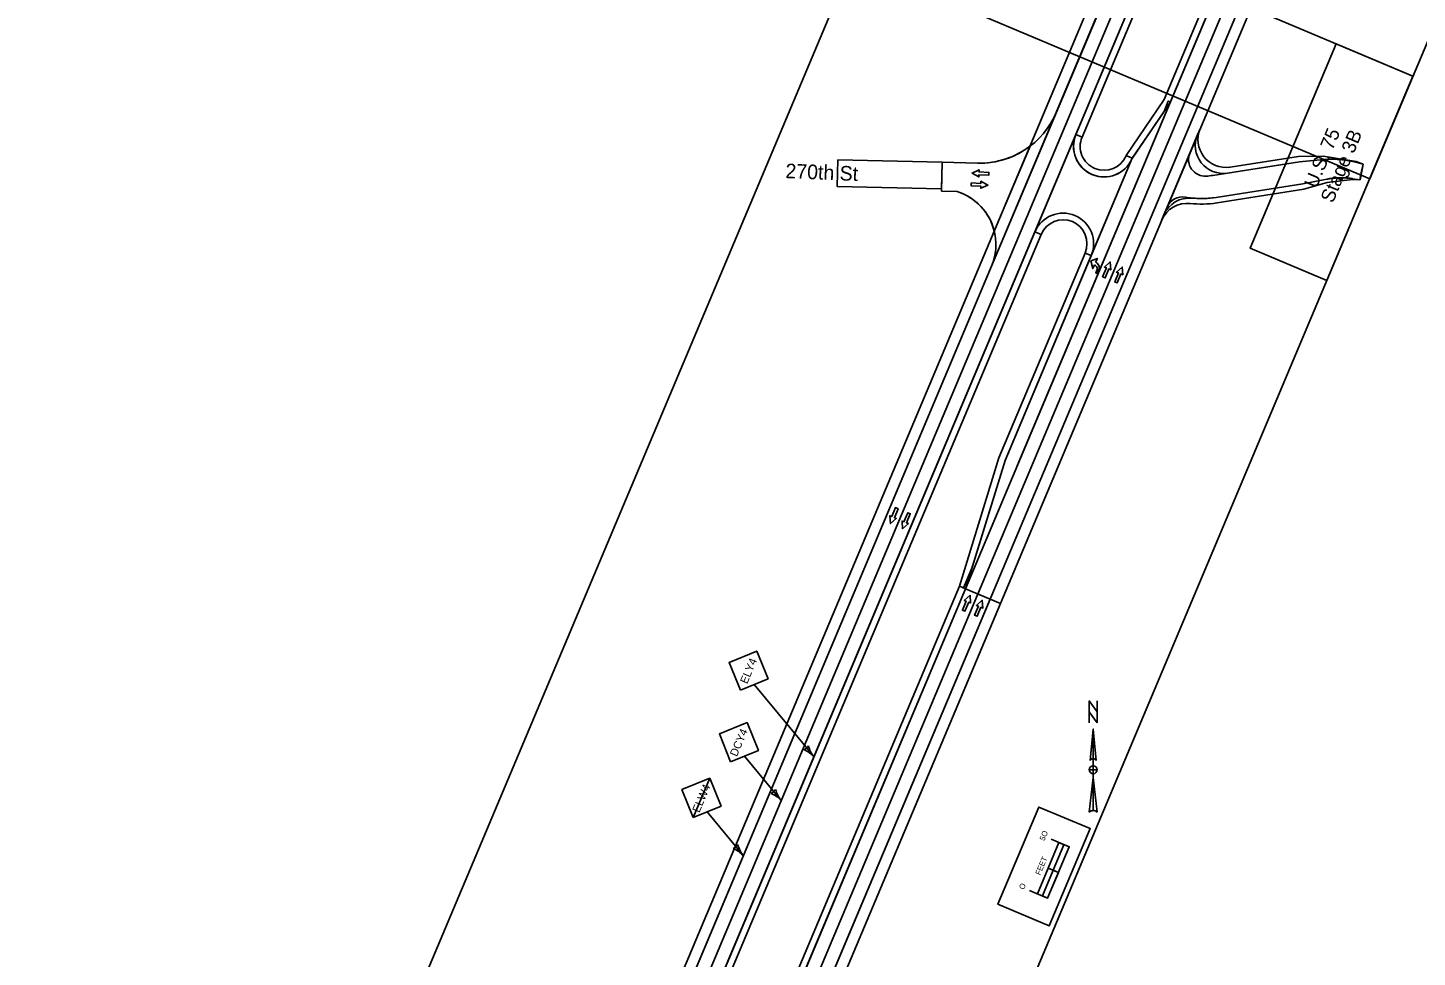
# Model space of a CAD drawing. Extents: x 14104283 to 14120882, y 8635219 to 8671666.
# Drawn here: x 14110477 to 14111728, y 8650037 to 8650873 of the extents above; entities that cross this region are included whole.
import ezdxf

# ---------------------------------------------------------------- set-up
doc = ezdxf.new("R2010")
doc.units = 0
for name, color, linetype in [('Cell', 7, 'Continuous'), ('dsnCellsNorthArrow', 7, 'Continuous'), ('dsnCellsScaleBlock', 7, 'Continuous'), ('dsnNonPlotable', 7, 'Continuous'), ('dsnPaintExistingBrokenLaneLineWhite', 7, 'Continuous'), ('dsnPaintExistingEdgeLineLeftYellow', 7, 'Continuous'), ('dsnPaintExistingEdgeLineRightWhite', 7, 'Continuous'), ('dsnPaintExistingLaneLineWhite', 7, 'Continuous'), ('dsnShadingGranular', 7, 'Continuous'), ('dsnShadingPaved', 7, 'Continuous'), ('dsnStdLabel', 7, 'Continuous'), ('dsnStgShadingPrevPav', 7, 'Continuous'), ('dsnTextFinalPlan', 7, 'Continuous'), ('dsnTextOverlapEven', 7, 'Continuous')]:
    doc.layers.add(name, color=color, linetype=linetype)

msp = doc.modelspace()

# ---------------------------------------------------------------- linework, layer by layer
at = {"layer": 'Cell'}
for p, q in [((14111438.2, 8650662.2), (14111438.4, 8650662.1)), ((14111437.4, 8650659.6), (14111437.1, 8650659.8))]:
    msp.add_line(p, q, dxfattribs=at)
for points in [[(14111342.1, 8650742.9), (14111342, 8650740.4), (14111333.2, 8650740.8), (14111333.1, 8650738.9), (14111327, 8650742.3), (14111333.4, 8650745.1), (14111333.3, 8650743.3)], [(14111326.1, 8650730.9), (14111326.2, 8650733.4), (14111335, 8650733), (14111335, 8650734.9), (14111341.2, 8650731.5), (14111334.8, 8650728.6), (14111334.9, 8650730.5)], [(14111446.9, 8650648), (14111444.5, 8650649), (14111447.9, 8650657.1), (14111446.1, 8650657.8), (14111451.4, 8650662.4), (14111451.9, 8650655.4), (14111450.2, 8650656.1)], [(14111457.7, 8650643.5), (14111455.4, 8650644.4), (14111458.7, 8650652.5), (14111456.9, 8650653.2), (14111462.2, 8650657.8), (14111462.7, 8650650.9), (14111461, 8650651.6)], [(14111258.1, 8650441.5), (14111260.4, 8650440.5), (14111257.1, 8650432.4), (14111258.8, 8650431.7), (14111253.5, 8650427.1), (14111253, 8650434.1), (14111254.7, 8650433.4)], [(14111269.1, 8650436.8), (14111271.4, 8650435.9), (14111268, 8650427.8), (14111269.8, 8650427.1), (14111264.5, 8650422.5), (14111264, 8650429.4), (14111265.7, 8650428.7)], [(14111320.6, 8650348.3), (14111318.3, 8650349.2), (14111321.6, 8650357.3), (14111319.9, 8650358), (14111325.2, 8650362.6), (14111325.7, 8650355.7), (14111324, 8650356.4)], [(14111331.6, 8650343.7), (14111329.3, 8650344.7), (14111332.7, 8650352.8), (14111330.9, 8650353.5), (14111336.2, 8650358.1), (14111336.7, 8650351.1), (14111335, 8650351.8)]]:
    msp.add_lwpolyline(points, close=True, dxfattribs=at)
for points in [[(14111333.3, 8650743.3), (14111333.4, 8650745.1), (14111327, 8650742.3), (14111333.1, 8650738.9), (14111333.2, 8650740.8), (14111342, 8650740.4), (14111342.1, 8650742.9), (14111333.3, 8650743.3)], [(14111334.9, 8650730.5), (14111334.8, 8650728.6), (14111341.2, 8650731.5), (14111335, 8650734.9), (14111335, 8650733), (14111326.2, 8650733.4), (14111326.1, 8650730.9), (14111334.9, 8650730.5)], [(14111434, 8650663.3), (14111439.8, 8650665.5), (14111438.2, 8650662.2)], [(14111434, 8650663.3), (14111439.8, 8650665.5), (14111438.2, 8650662.2)], [(14111437.1, 8650659.8), (14111435.6, 8650656.4), (14111434, 8650663.3)], [(14111437.1, 8650659.8), (14111435.6, 8650656.4), (14111434, 8650663.3)], [(14111438.2, 8650662.2), (14111438.4, 8650662.1)], [(14111450.2, 8650656.1), (14111451.9, 8650655.4), (14111451.4, 8650662.4), (14111446.1, 8650657.8), (14111447.9, 8650657.1), (14111444.5, 8650649), (14111446.9, 8650648), (14111450.2, 8650656.1)], [(14111437.4, 8650659.6), (14111437.1, 8650659.8)], [(14111441, 8650655.3), (14111439.7, 8650651.9), (14111438.3, 8650652.5), (14111439.3, 8650654.9)], [(14111441, 8650655.3), (14111439.7, 8650651.9), (14111438.3, 8650652.5), (14111439.3, 8650654.9)], [(14111461, 8650651.6), (14111462.7, 8650650.9), (14111462.2, 8650657.8), (14111456.9, 8650653.2), (14111458.7, 8650652.5), (14111455.4, 8650644.4), (14111457.7, 8650643.5), (14111461, 8650651.6)], [(14111254.7, 8650433.4), (14111253, 8650434.1), (14111253.5, 8650427.1), (14111258.8, 8650431.7), (14111257.1, 8650432.4), (14111260.4, 8650440.5), (14111258.1, 8650441.5), (14111254.7, 8650433.4)], [(14111265.7, 8650428.7), (14111264, 8650429.4), (14111264.5, 8650422.5), (14111269.8, 8650427.1), (14111268, 8650427.8), (14111271.4, 8650435.9), (14111269.1, 8650436.8), (14111265.7, 8650428.7)], [(14111324, 8650356.4), (14111325.7, 8650355.7), (14111325.2, 8650362.6), (14111319.9, 8650358), (14111321.6, 8650357.3), (14111318.3, 8650349.2), (14111320.6, 8650348.3), (14111324, 8650356.4)], [(14111335, 8650351.8), (14111336.7, 8650351.1), (14111336.2, 8650358.1), (14111330.9, 8650353.5), (14111332.7, 8650352.8), (14111329.3, 8650344.7), (14111331.6, 8650343.7), (14111335, 8650351.8)]]:
    msp.add_lwpolyline(points, dxfattribs=at)
for centre, major_axis in [((14111436, 8650656.2), (-1.38, -3.41)), ((14111436, 8650656.2), (-1.38, -3.41)), ((14111436.4, 8650657.2), (-1.97, -4.87)), ((14111436.4, 8650657.2), (-1.97, -4.87))]:
    msp.add_ellipse(centre, major_axis=major_axis, ratio=0.9474, start_param=1.570796, end_param=3.141593, dxfattribs=at)
at = {"layer": 'dsnCellsNorthArrow'}
for p, q in [((14111436, 8650242.3), (14111438.8, 8650214.1)), ((14111436, 8650242.3), (14111436, 8650169)), ((14111433.2, 8650214.1), (14111433.2, 8650214.1)), ((14111433.3, 8650214.4), (14111433.8, 8650215)), ((14111436, 8650202.1), (14111436, 8650202.1)), ((14111432.4, 8650167.6), (14111436, 8650198.6))]:
    msp.add_line(p, q, dxfattribs=at)
msp.add_lwpolyline([(14111439.5, 8650247.9), (14111432.4, 8650257.8), (14111432.4, 8650267.6), (14111439.5, 8650257.8)], close=True, dxfattribs=at)
for points in [[(14111432.4, 8650247.9), (14111432.4, 8650267.6), (14111439.5, 8650257.8), (14111439.5, 8650267.6)], [(14111433.2, 8650214.1), (14111436, 8650242.3), (14111436, 8650215.5)], [(14111436, 8650202.1), (14111436, 8650205.7), (14111432.4, 8650205.7)], [(14111439.5, 8650205.7), (14111436, 8650205.7), (14111436, 8650209.2)], [(14111436, 8650169), (14111436, 8650198.6), (14111439.5, 8650167.6)]]:
    msp.add_lwpolyline(points, dxfattribs=at)
for centre, radius, start, end in [((14111436, 8650212), 3.52, 90.0204, 143.1257), ((14111436, 8650212), 3.52, 36.8481, 90.0218), ((14111436, 8650205.7), 3.52, 90, 180), ((14111436, 8650205.7), 3.52, 180, 270), ((14111436, 8650205.7), 3.52, 0, 90), ((14111436, 8650205.7), 3.52, 270, 360), ((14111436, 8650163.9), 5.1, 89.9894, 133.619), ((14111436, 8650163.9), 5.11, 46.4021, 90.0006)]:
    msp.add_arc(centre, radius, start, end, dxfattribs=at)
at = {"layer": 'dsnCellsScaleBlock'}
msp.add_line((14111404.7, 8650113.3), (14111395.5, 8650117.2), dxfattribs=at)
msp.add_line((14111404.7, 8650113.3), (14111395.5, 8650117.2), dxfattribs=at)
for points in [[(14111396.4, 8650065.3), (14111350.3, 8650084.7), (14111387.2, 8650172.2), (14111433.3, 8650152.8)], [(14111350.3, 8650084.7), (14111387.2, 8650172.2), (14111433.3, 8650152.8), (14111396.4, 8650065.3)], [(14111396.4, 8650065.3), (14111350.3, 8650084.7), (14111387.2, 8650172.2), (14111433.3, 8650152.8)], [(14111400, 8650115.3), (14111409.7, 8650138.3), (14111405.2, 8650140.3), (14111395.5, 8650117.2)], [(14111395, 8650090.3), (14111404.7, 8650113.3), (14111400, 8650115.3), (14111390.3, 8650092.2)]]:
    msp.add_lwpolyline(points, close=True, dxfattribs=at)
for points in [[(14111378.8, 8650097.1), (14111395, 8650090.3), (14111414.4, 8650136.4), (14111398.3, 8650143.2)], [(14111385.8, 8650094.2), (14111405.2, 8650140.3)]]:
    msp.add_lwpolyline(points, dxfattribs=at)
at = {"layer": 'dsnNonPlotable'}
for points in [[(14111219.5, 8650933.3), (14111828.1, 8652377.8), (14112293.5, 8652181.8), (14111684.9, 8650737.2)], [(14110649.8, 8649580.9), (14111258.3, 8651025.5), (14111723.7, 8650829.4), (14111115.1, 8649384.9)]]:
    msp.add_lwpolyline(points, close=True, dxfattribs=at)
at = {"layer": 'dsnPaintExistingBrokenLaneLineWhite'}
for p, q in [((14110829.5, 8649404.5), (14118424.3, 8667439.6)), ((14110913.3, 8649369.2), (14114932.5, 8658913.4))]:
    msp.add_line(p, q, dxfattribs=at)
at = {"layer": 'dsnPaintExistingEdgeLineLeftYellow'}
for p, q in [((14113594.8, 8655940.3), (14111420.5, 8650777)), ((14111505.3, 8650805.9), (14113533.3, 8655621.7)), ((14111470.9, 8650755.1), (14111505.3, 8650805.9)), ((14111356.7, 8650483.8), (14111434.3, 8650668.1)), ((14111321.1, 8650368.5), (14111356.7, 8650483.8)), ((14110902.3, 8649373.8), (14111321.1, 8650368.5))]:
    msp.add_line(p, q, dxfattribs=at)
msp.add_lwpolyline([(14111383.6, 8650689.4), (14110840.5, 8649399.8), (14109233.5, 8645585.3)], dxfattribs=at)
for centre, start, end in [((14111445.8, 8650766.3), 157.1633, 335.8501), ((14111408.9, 8650678.8), 67.1633, 156.8935), ((14111408.9, 8650678.8), 337.1465, 67.1633)]:
    msp.add_arc(centre, 27.5, start, end, dxfattribs=at)
at = {"layer": 'dsnPaintExistingEdgeLineRightWhite'}
for p, q in [((14110924.4, 8649364.5), (14118874.7, 8668243.7)), ((14113555.5, 8655908.7), (14111402.9, 8650797.1))]:
    msp.add_line(p, q, dxfattribs=at)
msp.add_lwpolyline([(14111344.6, 8650658.6), (14110818.4, 8649409.2), (14109217, 8645608.1)], dxfattribs=at)
at = {"layer": 'dsnPaintExistingLaneLineWhite'}
msp.add_line((14111367.7, 8650479.1), (14111445.3, 8650663.4), dxfattribs=at)
at = {"layer": 'dsnShadingGranular'}
msp.add_line((14111523, 8650760.3), (14111502.5, 8650711.7), dxfattribs=at)
at = {"layer": 'dsnShadingPaved'}
for p, q in [((14111505.5, 8650806.3), (14113533.3, 8655621.7)), ((14113555.5, 8655612.4), (14110924.4, 8649364.5)), ((14111321.1, 8650368.5), (14111505.5, 8650806.3)), ((14111505.3, 8650805.7), (14111321.1, 8650368.5)), ((14111470.6, 8650754.6), (14111505.3, 8650805.7)), ((14111402.9, 8650797.1), (14111344.6, 8650658.6)), ((14111383.6, 8650689.4), (14111420.5, 8650777)), ((14111299.6, 8650726), (14111300.2, 8650752)), ((14111300.2, 8650752), (14111332, 8650751.3)), ((14111313.6, 8650725.7), (14111299.6, 8650726)), ((14111356.7, 8650483.8), (14111434.3, 8650668.1)), ((14111321.1, 8650368.5), (14111356.7, 8650483.8)), ((14110902.3, 8649373.8), (14111321.1, 8650368.5))]:
    msp.add_line(p, q, dxfattribs=at)
for points in [[(14118413.2, 8667444.3), (14110818.4, 8649409.2), (14109142.6, 8645431.4)], [(14109164.7, 8645422.1), (14110840.5, 8649399.8), (14118435.4, 8667434.9)]]:
    msp.add_lwpolyline(points, dxfattribs=at)
for centre, radius, start, end in [((14111333.8, 8650826.2), 75, 268.6633, 337.1633), ((14111445.8, 8650766.3), 27.5, 157.1801, 247.1633), ((14111445.8, 8650766.3), 27.5, 247.1633, 335.8501), ((14111298.5, 8650678), 50, 337.1633, 72.4031), ((14111408.9, 8650678.8), 27.5, 67.1633, 156.8935), ((14111408.9, 8650678.8), 27.5, 337.1465, 67.1633)]:
    msp.add_arc(centre, radius, start, end, dxfattribs=at)
at = {"layer": 'dsnStdLabel'}
for p, q in [((14111131, 8650282.4), (14111184.8, 8650217.3)), ((14111122.2, 8650218), (14111155.2, 8650178.1)), ((14111076.1, 8650162.8), (14111090.9, 8650198)), ((14111088.6, 8650167.9), (14111121.2, 8650128.3))]:
    msp.add_line(p, q, dxfattribs=at)
for points in [[(14111118.5, 8650277.3), (14111143.5, 8650287.5), (14111133.3, 8650312.5), (14111108.3, 8650302.3)], [(14111109.7, 8650212.9), (14111134.7, 8650223.1), (14111124.6, 8650248.1), (14111099.6, 8650237.9)], [(14111076.1, 8650162.8), (14111101.1, 8650173), (14111090.9, 8650198), (14111065.9, 8650187.8)]]:
    msp.add_lwpolyline(points, close=True, dxfattribs=at)
for centre, radius, start, end in [((14111172.2, 8650231.9), 8.86, 292.8385, 328.307), ((14111202.2, 8650232.2), 22.9, 192.5015, 220.5728), ((14111167.3, 8650202.4), 22.9, 40.5727, 68.6439), ((14111142.7, 8650192.7), 8.86, 292.8385, 328.307), ((14111172.6, 8650193), 22.9, 192.5015, 220.5728), ((14111137.8, 8650163.1), 22.9, 40.5727, 68.6439), ((14111108.7, 8650143), 8.86, 292.8385, 328.307), ((14111138.7, 8650143.3), 22.9, 192.5015, 220.5728), ((14111103.8, 8650113.4), 22.9, 40.5727, 68.6439)]:
    msp.add_arc(centre, radius, start, end, dxfattribs=at)
at = {"layer": 'dsnStgShadingPrevPav'}
for p, q in [((14110809.2, 8649413), (14118404, 8667448.1)), ((14118413.2, 8667444.3), (14110818.4, 8649409.2)), ((14113594.8, 8655940.3), (14111420.5, 8650777)), ((14111402.9, 8650797.1), (14113555.5, 8655908.7)), ((14113533.3, 8655621.7), (14111505.5, 8650806.3)), ((14111352.5, 8650355.3), (14113564.7, 8655608.5)), ((14111505.5, 8650806.3), (14111321.1, 8650368.5)), ((14111344.6, 8650658.6), (14111402.9, 8650797.1)), ((14111383.6, 8650689.4), (14111420.5, 8650777)), ((14111420.5, 8650777), (14111383.6, 8650689.4)), ((14111420.5, 8650777), (14111426, 8650774.7)), ((14111529.9, 8650776.7), (14111523, 8650760.3)), ((14111532.2, 8650782.1), (14111529.9, 8650776.7)), ((14111379.2, 8650766.5), (14111347, 8650690.1)), ((14111299.6, 8650726), (14111300.2, 8650752)), ((14111300.2, 8650752), (14111332, 8650751.3)), ((14111471.1, 8650755.6), (14111434.3, 8650668.1)), ((14111465.6, 8650758), (14111471.1, 8650755.6)), ((14111523, 8650760.3), (14111502.5, 8650711.7)), ((14111621.5, 8650752.4), (14111543.5, 8650740.2)), ((14111556.8, 8650742.3), (14111621.5, 8650752.4)), ((14111620.7, 8650757.3), (14111559.1, 8650747.7)), ((14111642.9, 8650757.4), (14111620.7, 8650757.3)), ((14111643.4, 8650754.4), (14111621.5, 8650752.4)), ((14111621.5, 8650752.4), (14111643.4, 8650754.4)), ((14111678.8, 8650750.4), (14111672.4, 8650752.1)), ((14111672.4, 8650752.1), (14111678.8, 8650750.4)), ((14111675.9, 8650736.2), (14111678.8, 8650750.4)), ((14111678.8, 8650750.4), (14111677.5, 8650744)), ((14111677.8, 8650744), (14111679, 8650750.3)), ((14111543.5, 8650740.2), (14111556.8, 8650742.3)), ((14111669.4, 8650737.2), (14111675.9, 8650736.2)), ((14111675.9, 8650736.2), (14111669.4, 8650737.2)), ((14111677.5, 8650744), (14111675.9, 8650736.2)), ((14111676.2, 8650736.1), (14111677.8, 8650744)), ((14111677.8, 8650744), (14111677.5, 8650744)), ((14111677.5, 8650744), (14111677.8, 8650744)), ((14111313.6, 8650725.7), (14111299.6, 8650726)), ((14111546.6, 8650720.4), (14111624.6, 8650732.6)), ((14111624.6, 8650732.6), (14111546.6, 8650720.4)), ((14111547.4, 8650715.5), (14111625.4, 8650727.7)), ((14111624.6, 8650732.6), (14111646.1, 8650736.8)), ((14111646.1, 8650736.8), (14111624.6, 8650732.6)), ((14111625.4, 8650727.7), (14111646.6, 8650733.8)), ((14111499.6, 8650704.6), (14111497.5, 8650699.8)), ((14111502.5, 8650711.7), (14111499.6, 8650704.6)), ((14111389.1, 8650687.1), (14111383.6, 8650689.4)), ((14111434.3, 8650668.1), (14111428.7, 8650670.4)), ((14111321.1, 8650368.5), (14111352.5, 8650355.3))]:
    msp.add_line(p, q, dxfattribs=at)
for points in [[(14113600.3, 8655938), (14111426, 8650774.7), (14111420.5, 8650777), (14113594.8, 8655940.3)], [(14111465.6, 8650758), (14111500, 8650808.6), (14113527.8, 8655624.1), (14113533.3, 8655621.7), (14111505.5, 8650806.3), (14111503.6, 8650807.1), (14111499.8, 8650797.8), (14111471.1, 8650755.6)], [(14111321.1, 8650368.5), (14111319.3, 8650369.3), (14111327.1, 8650387.7), (14111356.7, 8650483.8), (14111471.1, 8650755.6), (14111499.8, 8650797.8), (14111503.6, 8650807.1), (14111505.5, 8650806.3)], [(14111299.6, 8650728), (14111205.7, 8650730.2), (14111206.3, 8650754.2), (14111300.2, 8650752)], [(14109239, 8645583), (14111389.1, 8650687.1), (14111383.6, 8650689.4), (14109233.5, 8645585.3)], [(14111315.6, 8650370.9), (14111351.1, 8650486.1), (14111428.7, 8650670.4), (14111434.3, 8650668.1), (14111356.7, 8650483.8), (14111327.1, 8650387.7), (14111319.3, 8650369.3)], [(14110622.7, 8648725.7), (14111315.6, 8650370.9), (14111321.1, 8650368.5), (14110628.3, 8648723.4)], [(14110902.3, 8649373.8), (14110924.4, 8649364.5), (14111343.3, 8650359.2), (14111321.1, 8650368.5)], [(14110933.6, 8649360.6), (14111352.5, 8650355.3), (14111343.3, 8650359.2), (14110924.4, 8649364.5)]]:
    msp.add_lwpolyline(points, close=True, dxfattribs=at)
for points in [[(14111679, 8650750.3), (14111672.5, 8650752.7), (14111642.9, 8650757.4)], [(14111646.6, 8650733.8), (14111669.3, 8650736.6), (14111676.2, 8650736.1)], [(14111383.6, 8650689.4), (14110840.5, 8649399.8), (14109233.5, 8645585.3)], [(14109217, 8645608.1), (14110818.4, 8649409.2), (14111344.6, 8650658.6)]]:
    msp.add_lwpolyline(points, dxfattribs=at)
for centre, radius, start, end in [((14111445.8, 8650766.3), 21.5, 157.1633, 247.1633), ((14111552.9, 8650767), 25, 157.1633, 278.89), ((14111552.9, 8650767), 25, 157.1633, 278.89), ((14111555.2, 8650772.4), 25, 157.1633, 278.89), ((14111333.8, 8650826.2), 75, 268.6633, 307.2369), ((14111445.8, 8650766.3), 21.5, 247.1633, 337.1633), ((14111536.8, 8650754.5), 15, 157.1633, 273.9019), ((14111536.8, 8650754.5), 15, 157.1633, 273.9019), ((14111533.4, 8650804.4), 65, 273.9019, 278.89), ((14111533.4, 8650804.4), 65, 273.9019, 278.89), ((14111298.5, 8650678), 50, 14.0332, 72.4031), ((14111520.6, 8650690.1), 25, 83.5772, 157.1633), ((14111522.6, 8650694.9), 25, 84.3469, 157.1633), ((14111522.6, 8650694.9), 25, 84.3469, 157.1633), ((14111516.4, 8650705.9), 15, 80.1639, 157.1633), ((14111516.4, 8650705.9), 15, 80.1639, 157.1633), ((14111533.4, 8650804.4), 85, 260.1639, 278.89), ((14111533.4, 8650804.4), 85, 260.1639, 264.3457), ((14111533.4, 8650804.4), 90, 263.5772, 278.89), ((14111533.4, 8650804.4), 85, 264.3457, 278.89), ((14111408.9, 8650678.8), 21.5, 67.1633, 157.1633), ((14111408.9, 8650678.8), 21.5, 337.1633, 67.1633)]:
    msp.add_arc(centre, radius, start, end, dxfattribs=at)
for points in [[(14111672.4, 8650752.1), (14111671.9, 8650752.2), (14111671, 8650752.5), (14111669.6, 8650752.8), (14111668.2, 8650753.1), (14111666.7, 8650753.4), (14111665.3, 8650753.6), (14111663.9, 8650753.9), (14111662.4, 8650754.1), (14111661, 8650754.2), (14111659.5, 8650754.4), (14111658.1, 8650754.5), (14111656.6, 8650754.6), (14111655.1, 8650754.7), (14111653.7, 8650754.8), (14111652.2, 8650754.8), (14111650.7, 8650754.8), (14111649.3, 8650754.8), (14111647.8, 8650754.7), (14111646.3, 8650754.6), (14111644.8, 8650754.5), (14111643.9, 8650754.4), (14111643.4, 8650754.4)], [(14111643.4, 8650754.4), (14111643.9, 8650754.4), (14111644.8, 8650754.5), (14111646.3, 8650754.6), (14111647.8, 8650754.7), (14111649.3, 8650754.8), (14111650.7, 8650754.8), (14111652.2, 8650754.8), (14111653.7, 8650754.8), (14111655.1, 8650754.7), (14111656.6, 8650754.6), (14111658.1, 8650754.5), (14111659.5, 8650754.4), (14111661, 8650754.2), (14111662.4, 8650754.1), (14111663.9, 8650753.9), (14111665.3, 8650753.6), (14111666.7, 8650753.4), (14111668.2, 8650753.1), (14111669.6, 8650752.8), (14111671, 8650752.5), (14111671.9, 8650752.2), (14111672.4, 8650752.1)], [(14111646.1, 8650736.8), (14111646.5, 8650736.9), (14111647.3, 8650737), (14111648.4, 8650737.2), (14111649.6, 8650737.4), (14111650.7, 8650737.5), (14111651.9, 8650737.7), (14111653, 8650737.8), (14111654.2, 8650737.9), (14111655.4, 8650738), (14111656.5, 8650738), (14111657.7, 8650738), (14111658.9, 8650738.1), (14111660.1, 8650738.1), (14111661.2, 8650738), (14111662.4, 8650738), (14111663.6, 8650737.9), (14111664.7, 8650737.8), (14111665.9, 8650737.7), (14111667.1, 8650737.6), (14111668.2, 8650737.4), (14111669, 8650737.3), (14111669.4, 8650737.2)], [(14111669.4, 8650737.2), (14111669, 8650737.3), (14111668.2, 8650737.4), (14111667.1, 8650737.6), (14111665.9, 8650737.7), (14111664.7, 8650737.8), (14111663.6, 8650737.9), (14111662.4, 8650738), (14111661.2, 8650738), (14111660.1, 8650738.1), (14111658.9, 8650738.1), (14111657.7, 8650738), (14111656.5, 8650738), (14111655.4, 8650738), (14111654.2, 8650737.9), (14111653, 8650737.8), (14111651.9, 8650737.7), (14111650.7, 8650737.5), (14111649.6, 8650737.4), (14111648.4, 8650737.2), (14111647.3, 8650737), (14111646.5, 8650736.9), (14111646.1, 8650736.8)]]:
    msp.add_open_spline(points, degree=3, dxfattribs=at)
at = {"layer": 'dsnTextOverlapEven'}
for points in [[(14111723.7, 8650829.4), (14111646.3, 8650645.7), (14111577.2, 8650674.9), (14111654.6, 8650858.5)], [(14111577.2, 8650674.9), (14111654.6, 8650858.5), (14111723.7, 8650829.4), (14111646.3, 8650645.7)]]:
    msp.add_lwpolyline(points, close=True, dxfattribs=at)

# ---------------------------------------------------------------- texts
at = {"layer": 'dsnCellsScaleBlock'}
for s, p in [('5O', (14111392.1, 8650141.4)), ('FEET', (14111388.3, 8650110.5)), ('O', (14111373.6, 8650097.5))]:
    msp.add_text(s, height=5, rotation=67.1547, dxfattribs=at).set_placement(p)
at = {"layer": 'dsnStdLabel'}
for s, p in [('ELY4', (14111124.6, 8650282.4)), ('DCY4', (14111115.4, 8650217)), ('ELW4', (14111081.6, 8650166.6))]:
    msp.add_text(s, height=7.2, rotation=67.1547, dxfattribs=at).set_placement(p)
at = {"layer": 'dsnTextFinalPlan'}
msp.add_text('270th St', height=13.12, rotation=357.6374, dxfattribs=at).set_placement((14111158.9, 8650737.8))
at = {"layer": 'dsnTextOverlapEven'}
for s, p in [('U.S. 75', (14111636.9, 8650727.9)), ('Stage 3B', (14111651.6, 8650714.6))]:
    msp.add_text(s, height=12.5, rotation=67.1547, dxfattribs=at).set_placement(p)

doc.saveas('drawing.dxf')
